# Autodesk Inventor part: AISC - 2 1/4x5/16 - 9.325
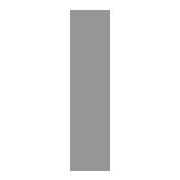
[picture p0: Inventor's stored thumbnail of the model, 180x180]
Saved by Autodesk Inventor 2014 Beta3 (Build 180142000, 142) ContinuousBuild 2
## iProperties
_CCFamilyMember: 149
_CCFamilyDisplayName: ANSI AISC (Rectangular) - Flat Bar Steel
_FrameMemberDoc: Frame Member File
_Version: 15.0.0
_GetPNFromCC: 1
Created: 2010-11
Part Number: AISC - 2 1/4x5/16 - 9.325
Material: Steel, Mild
Description: Flat Bar Steel
Document SubType Name: Modeling
Standard: ANSI
Designer: Beta-8540w
Standards Organization: ANSI
Language: en-US
Size Designation: 2 1/4x5/16
Categories: <MemberInstance><Categories><Category DisplayName="Structural Shapes" InternalName="089c4875-fa83-4c05-b084-43b9cc11f5ed" Mnemonic="GRDR"><CategoryParameter Dis
Stock Number: 2 1/4x5/16
Density: 7.86 g/cm^3
Appearance: Steel
IsCustomPart: 1
G_L: 9.325 in
G_W: 0.313 in
G_H: 2.250 in
Author: Beta-8540w
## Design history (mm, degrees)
node "Start plane"
node "End plane"
node "Driven Length"
  sketch "Sketch3"
    geometry: L1 (0, 0)-(10, 0) reference
    constraints: 2 end point, 1 horizontal
  workplane "Work Plane3"
  sketch "Sketch4"
    geometry: L1 (-2, 0)-(12, 0) reference; L2 (-40.005, 236.864)-(40.005, 236.864) reference
    dimensions: "d9" = 236.86413 distance between parallel lines of L1 L2 (derived)
sketch "Sweep Path"
  geometry: L1 through (25.4, 40.279) direction (-1, 0); L2 through (112.121, 127) direction (-1, 0); 9 other entities
  constraints: 10 horizontal
node "Orientation Work Plane"
feature "Body" dims "d10" = 0
body "Solid1"
sketch "Sketch"
  geometry: L1 (3.969, -28.575)-(-3.969, -28.575); L2 (-3.969, -28.575)-(-3.969, 28.575); L3 (-3.969, 28.575)-(3.969, 28.575); L4 (3.969, 28.575)-(3.969, -28.575); L5 (-6, 0)-(8, 0); L6 (0, -30)-(0, 40); L7 (0, 54)-(0, -44); L8 (-9.2, 0)-(13.2, 0)
  constraints: 16 end point, 2 collinear, 2 parallel, 1 horizontal, 1 perpendicular
  dimensions: "d0" = 57.15 distance between parallel lines of L3 L1 (= G_W); "d1" = 7.9375 distance between parallel lines of L4 L2 (= G_H); "d4" = 3.96875 distance between parallel lines of L6 L4 (= 0.5 x d1); "d5" = 28.575 distance between parallel lines of L5 L3 (= 0.5 x d0)
other parameters: "G_W" = 57.15 [user parameter; used in 1 equation term], "G_H" = 7.9375 [user parameter; used in 1 equation term], "G_L" = 236.86413 (= d9) [user parameter], "G_OFFSET_START" = 0 [user parameter; used in 1 equation term], "G_OFFSET_END" = 0 [user parameter; used in 1 equation term], "d6" = 0 (computed from G_OFFSET_START), "d7" = 236.86413 (= G_OFFSET_END + B_L), "B_L" = 236.86413 [user parameter; used in 1 equation term], "d8" = 90 deg
